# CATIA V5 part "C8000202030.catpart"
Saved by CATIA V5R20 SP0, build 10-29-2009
Part number: C8000202030
Source: Unknown
Property "A": "34"
Property "ARTICLENO": "C8000202030"
Property "B": "16"
Property "BOMINFO": "C8000202030"
Property "C": "57"
Property "CA": "C8000202030"
Property "D1": "50"
Property "DES": "ROTATING EYEBOLT WITH RING Ton 2 M20x30"
Property "E": "61"
Property "H": "131"
Property "L": "30"
Property "LINA": "C8000202030"
Property "NB": "C8000202030"
Property "NBSYN": "$CODE."
Property "NN": "C800"
Property "NT": "Rotating eyebolt with ring"
Property "SIZE": "M20"
Property "SUPPLIER": "CF"
Property "SW": "40"
Property "WEIGHT": "1050"
Property "WLL": "2.00"
Bounding box of the stored display mesh (mm): x -33 to 33, y -30 to 146.819, z -25 to 25
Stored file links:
  C:\Users\Utente\Desktop\3D files 800\C8000202030.catpart
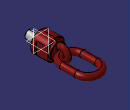
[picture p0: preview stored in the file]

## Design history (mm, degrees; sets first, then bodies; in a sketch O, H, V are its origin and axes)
Body1 "Geometry.1" (main body)
  Solid1 "C8000202030.catpart": solid without history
